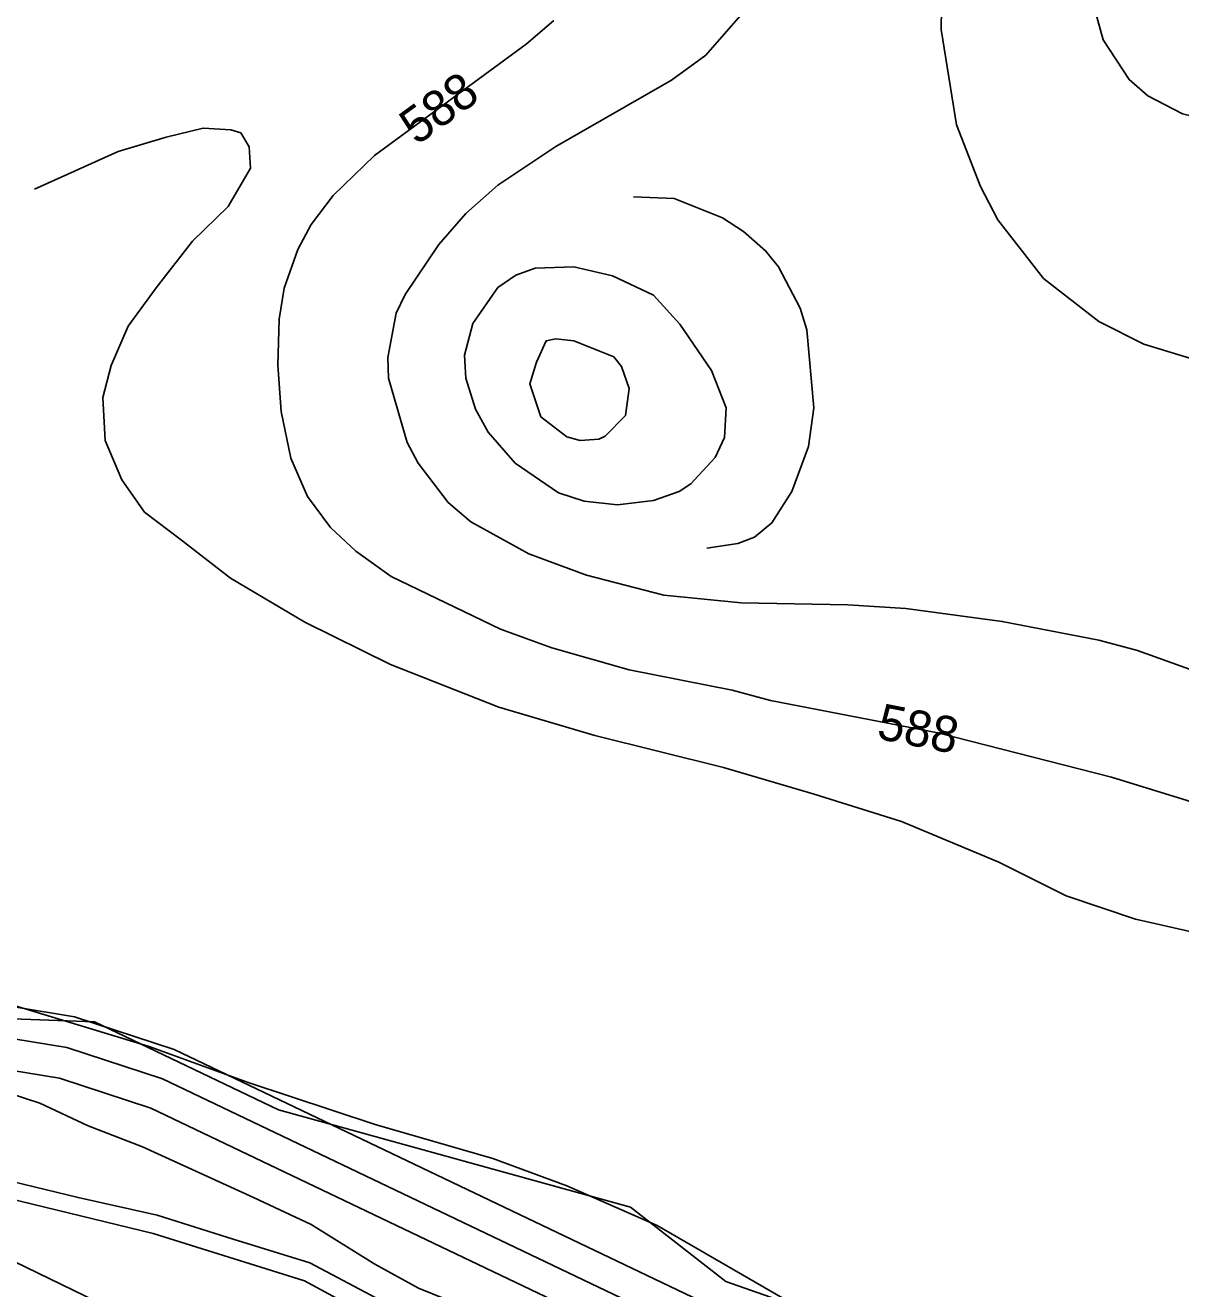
# Model space of a CAD drawing. Extents: x -709418 to -703832, y -1161719 to -1157826.
# Drawn here: x -705400.4 to -705143.5, y -1159483.1 to -1159202.3 of the extents above; entities that cross this region are included whole.
import ezdxf

# ---------------------------------------------------------------- set-up
doc = ezdxf.new("R2010")
doc.units = 0
for name, color, linetype in [('102_obvod PÚ', 7, 'Continuous'), ('103_hranice KÚ', 7, 'Continuous'), ('120_vrstevnice hlavní', 7, 'Continuous'), ('121_vrstevnice hlavní_popis', 7, 'Continuous'), ('122_vrstevnice základní', 7, 'Continuous'), ('124_vrstevnice doplňková', 7, 'Continuous'), ('201_orná půda_KN', 7, 'Continuous'), ('708_el NN nadzemní a podzemní_ E.ON', 7, 'Continuous'), ('735_OP sítí TI', 7, 'Continuous')]:
    doc.layers.add(name, color=color, linetype=linetype)

msp = doc.modelspace()

# ---------------------------------------------------------------- linework, layer by layer
at = {"layer": '102_obvod PÚ'}
msp.add_lwpolyline([(-705405.69, -1159458.61), (-705388.63, -1159462.82), (-705371.01, -1159466.68), (-705354.17, -1159472.03), (-705337.11, -1159477.31), (-705321.2, -1159485.73)], dxfattribs=at)
at = {"layer": '103_hranice KÚ'}
msp.add_lwpolyline([(-705225.01, -1159488.33), (-705244.62, -1159481.43), (-705265.81, -1159464.97), (-705344.08, -1159443.34), (-705385, -1159423.78), (-705409.33, -1159422.89), (-705434.44, -1159402.64), (-705455.51, -1159396.18), (-705483.68, -1159375.34), (-705500.95, -1159391.28), (-705509.01, -1159386.99), (-705524.52, -1159378.74), (-705538.64, -1159371.35), (-705553.14, -1159353), (-705564.11, -1159324.58), (-705575.14, -1159274.02), (-705584.26, -1159235.35), (-705586.94, -1159233.79), (-705610.07, -1159218.91), (-705650.29, -1159207.21), (-705680.34, -1159202.12)], dxfattribs=at)
at = {"layer": '120_vrstevnice hlavní'}
for points in [[(-705239.81, -1159198.33), (-705249.11, -1159208.91), (-705256.69, -1159214.49), (-705282.43, -1159229.22), (-705295.3, -1159237.8), (-705302.45, -1159244.09), (-705308.46, -1159250.96), (-705315.9, -1159262.11), (-705317.9, -1159266.26), (-705319.76, -1159276.13), (-705319.61, -1159280.7), (-705315.47, -1159295.01), (-705313.04, -1159299.58), (-705306.32, -1159308.31), (-705301.31, -1159312.59), (-705288.44, -1159319.75), (-705275.57, -1159324.47), (-705258.41, -1159328.9), (-705241.24, -1159330.61), (-705217.5, -1159331.04), (-705204.63, -1159331.9), (-705183.18, -1159334.76), (-705161.73, -1159338.91), (-705153.15, -1159341.2), (-705135.99, -1159347.35)], [(-705160.73, -1159205.48), (-705163.16, -1159196.9)], [(-705106.38, -1159198.04), (-705108.96, -1159206.62), (-705110.96, -1159210.91), (-705115.68, -1159217.49), (-705119.66, -1159221.34), (-705125.24, -1159224.14), (-705132.98, -1159224.36), (-705143.14, -1159221.93), (-705150.86, -1159217.92), (-705155.01, -1159214.34), (-705160.73, -1159205.48)], [(-705381.94, -1159487.18), (-705402.79, -1159477.04), (-705418.64, -1159469.88), (-705430.98, -1159461.82), (-705443.17, -1159452.24), (-705458.78, -1159437.51), (-705473.54, -1159423.6), (-705487.44, -1159411.53), (-705504.82, -1159398.74), (-705529.51, -1159387.8), (-705556.73, -1159375.81), (-705566.74, -1159370.95), (-705582.9, -1159360.93), (-705616.08, -1159335.48), (-705651.3, -1159309.45), (-705669.87, -1159299.28), (-705683.68, -1159294.6), (-705693.07, -1159292.84), (-705700.93, -1159292.46), (-705712.13, -1159293.77), (-705722.22, -1159296.11)]]:
    msp.add_lwpolyline(points, dxfattribs=at)
at = {"layer": '122_vrstevnice základní'}
for points in [[(-705282.86, -1159201.19), (-705289.01, -1159206.48), (-705322.76, -1159231.22), (-705331.92, -1159240.09), (-705336.78, -1159246.52), (-705339.78, -1159252.1), (-705342.78, -1159260.68), (-705343.93, -1159267.55), (-705344.21, -1159277.84), (-705343.5, -1159288.14), (-705341.35, -1159298.44), (-705337.64, -1159307.02), (-705332.49, -1159313.88), (-705326.91, -1159319.18), (-705319.04, -1159324.75), (-705294.73, -1159336.48), (-705283.29, -1159340.63), (-705266.13, -1159345.49), (-705243.25, -1159350.07), (-705234.67, -1159352.35), (-705197.48, -1159359.5), (-705158.87, -1159369.37), (-705133.16, -1159377.3)], [(-705398.28, -1159238.71), (-705379.68, -1159230.32), (-705369.06, -1159227.12), (-705360.84, -1159225.11), (-705354.69, -1159225.48), (-705352.47, -1159226.18), (-705350.6, -1159229.27), (-705350.28, -1159234.05), (-705355.28, -1159242.58), (-705363.19, -1159250.24), (-705371.28, -1159260.63), (-705377.47, -1159269.15), (-705381.28, -1159277.85), (-705383.1, -1159284.97), (-705382.63, -1159294.55), (-705378.91, -1159303.29), (-705373.82, -1159310.5), (-705365.64, -1159316.69), (-705354.74, -1159325.12), (-705338.2, -1159334.95), (-705319.15, -1159344.31), (-705295.08, -1159353.83), (-705273.74, -1159360.09)], [(-705244.96, -1159293.86), (-705244.53, -1159287.28), (-705247.82, -1159278.99), (-705254.83, -1159268.69), (-705260.69, -1159262.26), (-705269.85, -1159257.97), (-705278.43, -1159255.96), (-705287.01, -1159256.25), (-705291.3, -1159257.82), (-705295.3, -1159260.54), (-705300.9, -1159268.54), (-705302.74, -1159275.56), (-705302.45, -1159280.7), (-705300.31, -1159287.57), (-705297.45, -1159292.72), (-705291.44, -1159299.58), (-705281.86, -1159306.16), (-705276.14, -1159308.02), (-705268.7, -1159308.88), (-705260.69, -1159307.88), (-705254.97, -1159305.87), (-705252.4, -1159304.16), (-705246.97, -1159298.3), (-705244.96, -1159293.86)], [(-705273.74, -1159360.09), (-705245.17, -1159367.22), (-705225.02, -1159373.13), (-705205.56, -1159379.21), (-705183.96, -1159388.29), (-705168.95, -1159395.71), (-705153.59, -1159400.92), (-705140.43, -1159403.89), (-705125, -1159405.73), (-705114.76, -1159408.17), (-705105.71, -1159412.49), (-705096.85, -1159418.01), (-705089.02, -1159424.89), (-705064.89, -1159451.56), (-705051.78, -1159462.4), (-705044.1, -1159466.2), (-705037.11, -1159470.68), (-705033.38, -1159475.65), (-705032.38, -1159480.28), (-705032.74, -1159485.92), (-705033.97, -1159490.87), (-705035.36, -1159495.82)], [(-705184.99, -1159513.55), (-705204.6, -1159500.63), (-705230, -1159486.31), (-705259.87, -1159468.99), (-705280, -1159460.17), (-705296.39, -1159454.1), (-705322.61, -1159446.57), (-705350.78, -1159437.2), (-705372.8, -1159429.22), (-705402.11, -1159420.31), (-705420.38, -1159413.38), (-705436.75, -1159405.26), (-705449.37, -1159398.53), (-705474.22, -1159384.97), (-705486.15, -1159376.87), (-705490.06, -1159372.24), (-705491.08, -1159370.18)], [(-705300.15, -1159488.14), (-705312.94, -1159482.95), (-705322.66, -1159477.6), (-705336.8, -1159468.82), (-705349.59, -1159462.77), (-705374.26, -1159451.54), (-705386.37, -1159446.87), (-705397.11, -1159441.86), (-705410.13, -1159437.57), (-705423.1, -1159432.89), (-705431.62, -1159427.89), (-705443.03, -1159419.63), (-705453.75, -1159411.21), (-705478.41, -1159396.31), (-705497.35, -1159387.36), (-705506.91, -1159384.06)]]:
    msp.add_lwpolyline(points, dxfattribs=at)
at = {"layer": '124_vrstevnice doplňková'}
for points in [[(-705196.62, -1159193.75), (-705196.77, -1159203.19), (-705193.33, -1159224.36), (-705188.04, -1159238.09), (-705184.18, -1159245.52), (-705174.03, -1159258.54), (-705161.73, -1159268.12), (-705151.72, -1159273.12), (-705124.97, -1159281.28)], [(-705248.82, -1159318.46), (-705241.96, -1159317.46), (-705238.24, -1159316.03), (-705234.38, -1159312.88), (-705229.95, -1159305.87), (-705226.23, -1159295.86), (-705225.08, -1159287.28), (-705226.66, -1159269.98), (-705228.09, -1159265.11), (-705232.95, -1159255.96), (-705235.81, -1159252.39), (-705240.67, -1159248.1), (-705245.39, -1159245.09), (-705256.12, -1159240.8), (-705265.13, -1159240.37)], [(-705267.84, -1159278.13), (-705269.56, -1159275.98), (-705278.43, -1159272.41), (-705282.43, -1159271.98), (-705284.58, -1159272.41), (-705286.74, -1159277.13), (-705288.16, -1159281.98), (-705285.72, -1159289.28), (-705280, -1159293.72), (-705277, -1159294.58), (-705272.85, -1159294.29), (-705271.42, -1159293.57), (-705266.94, -1159288.97), (-705266.13, -1159282.99), (-705267.84, -1159278.13)]]:
    msp.add_lwpolyline(points, dxfattribs=at)
at = {"layer": '201_orná půda_KN'}
for p, q in [((-705429.01, -1159456.91), (-705371.93, -1159470.79)), ((-705371.93, -1159470.79), (-705429.01, -1159456.91)), ((-705405.69, -1159458.61), (-705388.63, -1159462.82)), ((-705388.63, -1159462.82), (-705371.01, -1159466.68)), ((-705371.01, -1159466.68), (-705354.17, -1159472.03)), ((-705371.93, -1159470.79), (-705338.28, -1159481.28)), ((-705338.28, -1159481.28), (-705371.93, -1159470.79)), ((-705354.17, -1159472.03), (-705337.11, -1159477.31)), ((-705337.11, -1159477.31), (-705321.2, -1159485.73)), ((-705338.28, -1159481.28), (-705306.42, -1159498.51)), ((-705306.42, -1159498.51), (-705338.28, -1159481.28))]:
    msp.add_line(p, q, dxfattribs=at)
at = {"layer": '708_el NN nadzemní a podzemní_ E.ON'}
msp.add_lwpolyline([(-705466.35, -1159394.29), (-705417.95, -1159425.05), (-705391.08, -1159429.47), (-705369.86, -1159436.43), (-705211.18, -1159512.22), (-705197.54, -1159525.99), (-705180.35, -1159559.09), (-705159.37, -1159644.15), (-705153.76, -1159644.98), (-705153.4, -1159644.86)], dxfattribs=at)
at = {"layer": '735_OP sítí TI'}
for points in [[(-705462.59, -1159388.39), (-705415.4, -1159418.37), (-705389.41, -1159422.65), (-705367.25, -1159429.92), (-705207.06, -1159506.43), (-705191.82, -1159521.82), (-705173.75, -1159556.6), (-705153.71, -1159637.87)], [(-705470.1, -1159400.2), (-705420.5, -1159431.73), (-705392.75, -1159436.29), (-705372.47, -1159442.94), (-705215.3, -1159518.01), (-705203.26, -1159530.16), (-705186.95, -1159561.58), (-705165.04, -1159650.38), (-705153.13, -1159652.15), (-705151.19, -1159651.5)]]:
    msp.add_lwpolyline(points, dxfattribs=at)

# ---------------------------------------------------------------- texts
at = {"layer": '121_vrstevnice hlavní_popis'}
for rotation, p in [(36.0518, (-705313.33, -1159229.09)), (348.8175, (-705211.33, -1159360.76))]:
    msp.add_text('588', height=8, rotation=rotation, dxfattribs=at).set_placement(p)

doc.saveas('drawing.dxf')
